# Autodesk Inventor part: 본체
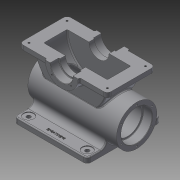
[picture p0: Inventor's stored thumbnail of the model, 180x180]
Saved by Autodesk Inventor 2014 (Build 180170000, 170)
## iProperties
Created: 2023-06
Part Number: 본체
Material: 알루미늄 6061
Document SubType Name: Modeling
Designer: mdu-01
Mass: 5644.39 g
Surface Area: 2847.06 cm^2
Volume: 2082.8 cm^3
Density: 2.71 g/cm^3
Appearance: 알루미늄 - 평지
Author: mdu-01
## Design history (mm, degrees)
sketch "스케치1"
  geometry: L1 (0, 70)-(0, -70); L2 (0, 0)-(-100, 0); L3 (0, 70)-(-45, 70); L4 (-45, 70)-(-45, 45); L5 (-45, 45)-(-100, 45); L6 (0, -70)-(-45, -70); L7 (-45, -70)-(-45, -45); L8 (-45, -45)-(-100, -45); L9 (-100, 45)-(-100, -45); 1 further point
  constraints: 18 end point, 3 perpendicular, 3 symmetric about line, 2 midpoint, 2 parallel, 1 coincident, 1 vertical
  dimensions: "d0" = 140 distance of L1.start L1.end; "d1" = 100 distance of L2.start L2.end; "d3" = 90 diameter of L4 L1; "d4" = 90 distance between parallel lines of L8 L5
revolve "회전1" sketch "스케치1" stored, may be unused: angle "d5" = 180 deg
sketch "스케치2"
  geometry: L1 (-155, -20)-(65, -20); L2 (75, -10)-(75, 100); L3 (65, 110)-(-155, 110); L4 (-165, 100)-(-165, -10); L5 (-165, -20)-(75, 110); L6 (75, -20)-(-165, 110); A1 r 10 centre (-155, 100) between (-155, 110) and (-165, 100); A2 r 10 centre (65, 100) between (75, 100) and (65, 110); A3 r 10 centre (65, -10) between (65, -20) and (75, -10); A4 r 10 centre (-155, -10) between (-165, -10) and (-155, -20); 1 further point
  constraints: 12 end point, 8 point on circle, 8 point on line, 8 tangent, 4 centre point, 3 equal radius, 2 midpoint, 2 parallel, 1 horizontal, 1 perpendicular
  dimensions: "d6" = 240 distance of L6.end L5.end; "d7" = 130 distance of L5.end L6.start; "d8" = 10 radius of A1
extrude "돌출1" join sketch "스케치2" distance "d9" = 15; taper "d10" = 0 deg
sketch "스케치3"
  geometry: C1 r 55 at (-100, 0); 1 further point
  constraints: 1 centre point
  dimensions: "d11" = 110 diameter of C1; "d12" = 100 distance of C1.centre point (0, 0)
extrude "돌출2" join sketch "스케치3" distance "d13" = 135; taper "d15" = 0 deg; dims "d14" = 107, "d16" = 0
sketch "스케치4"
  geometry: L1 (-100, -160)-(100, -160); L2 (100, -160)-(100, -145); L3 (100, -145)-(-100, -145); L4 (-100, -145)-(-100, -160); 1 further point
  constraints: 8 end point, 2 parallel, 1 horizontal, 1 perpendicular
  dimensions: "d17" = 200 distance of L3.end L2.end; "d18" = 15 distance of L2.end L1.end; "d19" = 100 distance from line of L4 point (0, 0); "d20" = 160 distance from line of L1 point (0, 0)
extrude "돌출3" join sketch "스케치4" stored distance "d21" = 200; taper "d22" = 0 deg
fillet "모깎기1" dims "d23" = 15
fillet "모깎기2" dims "d24" = 10
sketch "스케치5"
  geometry: L1 (0, 70)-(0, -70); L2 (-45, 70)-(0, 70) reference; L3 (-45, -70)-(0, -70) reference; L4 (-31, 70)-(-31, 48); L5 (-30, 47)-(-27.5, 47); L6 (-27.5, 47)-(-27.5, 32); L7 (-27.5, 32)-(-87, 32); L8 (0, 0)-(-91.923, 0); L9 (-31, -70)-(-31, -48); L10 (-30, -47)-(-27.5, -47); L11 (-27.5, -47)-(-27.5, -32); L12 (-27.5, -32)-(-87, -32); L13 (-87, 32)-(-87, -32); L14 (-31, 70)-(0, 70); L15 (-31, -70)-(0, -70); A1 r 1 centre (-30, 48) between (-31, 48) and (-30, 47); A2 r 1 centre (-30, -48) between (-30, -47) and (-31, -48)
  constraints: 26 end point, 7 symmetric about line, 4 parallel, 4 point on circle, 3 perpendicular, 2 centre point, 2 tangent, 1 collinear, 1 point on line, 1 vertical, 1 other
  dimensions: "d25" = 1 radius of A1; "d26" = 62 diameter of L4 L1; "d27" = 23 distance between parallel lines of L2 L5; "d28" = 64 distance between parallel lines of L12 L7; "d29" = 55 diameter of L6 L1; "d30" = 87 distance between parallel lines of L13 L1
revolve "회전2" sketch "스케치5" stored, may be unused: angle "d31" = 180 deg
sketch "스케치6"
  geometry: L1 (-107, -45)-(-107, -155) reference; L2 (135, -155)-(135, -45) reference; L3 (-107, -100)-(135, -100); L4 (-107, -142.5)-(-83.1, -142.5); L5 (-82, -141.4)-(-82, -138.5); L6 (-82, -138.5)-(110, -138.5); L7 (110, -138.5)-(110, -141.4); L8 (111.1, -142.5)-(135, -142.5); A1 r 1.1 centre (-83.1, -141.4) between (-83.1, -142.5) and (-82, -141.4); A2 r 1.1 centre (111.1, -141.4) between (110, -141.4) and (111.1, -142.5); 1 further point
  constraints: 12 end point, 4 point on circle, 4 tangent, 3 parallel, 2 centre point, 2 collinear, 2 midpoint, 2 perpendicular, 2 point on line, 1 equal radius
  dimensions: "d32" = 1.1 radius of A1; "d33" = 25 distance between parallel lines of L5 L1; "d34" = 77 diameter of L6 L3; "d35" = 85 diameter of L4 L3
revolve "회전3" sketch "스케치6" stored, may be unused: angle "d36" = 180 deg
fillet "모깎기3" dims "d37" = 3
fillet "모깎기4" dims "d38" = 3
sketch "스케치7"
  geometry: L1 (17, -16.754)-(177, -16.754); L2 (177, -16.754)-(177, 143.246); L3 (177, 143.246)-(17, 143.246); L4 (17, 143.246)-(17, -16.754); L5 (17, -16.754)-(177, 143.246); L6 (177, -16.754)-(17, 143.246); 1 further point
  constraints: 12 end point, 2 midpoint, 2 parallel, 1 horizontal, 1 perpendicular
  dimensions: "d39" = 160 distance of L3.end L2.end; "d40" = 160 distance of L2.end L1.end
hole "구멍1" sketch "스케치7" at (17, -16.754), (177, -16.754), (177, 143.246), (17, 143.246) diameter "d41" = 11; stored, may be unused: countersink angle "d45" = 90 deg, drill point angle "d47" = 118 deg; dims "d42" = 6, "d43" = 28, "d44" = 2, "d46" = 8
sketch "스케치8"
  geometry: L1 (-227, 3)-(-13, 3); L2 (-13, 3)-(-13, 107); L3 (-13, 107)-(-227, 107); L4 (-227, 107)-(-227, 3); L5 (-227, 3)-(-13, 107); L6 (-13, 3)-(-227, 107); 1 further point
  constraints: 12 end point, 2 midpoint, 2 parallel, 1 horizontal, 1 perpendicular
  dimensions: "d48" = 214 distance of L3.end L2.end; "d49" = 104 distance of L2.end L1.end
hole "구멍2" sketch "스케치8" at (-227, 3), (-13, 3), (-13, 107), (-227, 107) diameter "d50" = 4.917; stored, may be unused: countersink angle "d54" = 90 deg, drill point angle "d56" = 118 deg; dims "d51" = 15, "d52" = 4, "d53" = 7.5, "d55" = 15
sketch "스케치9"
  geometry: A1 r 37 centre (0, 0) between (-26.163, -26.163) and (26.163, -26.163); 1 further point
  constraints: 2 point on circle, 1 centre point, 1 coincident, 1 horizontal alignment
  dimensions: "d57" = 37 radius of A1; "d58" = 90 deg dimension on A1.centre A1.end A1.start
hole "구멍3" sketch "스케치9" at (-26.163, -26.163), (26.163, -26.163) diameter "d60" = 4.134; stored, may be unused: countersink angle "d64" = 90 deg, drill point angle "d66" = 118 deg; dims "d61" = 10, "d62" = 4, "d63" = 7.5, "d65" = 12
sketch "스케치10" dims "d68" = 97
  geometry: C1 r 38.5 at (0, 0) reference; 3 further points
  constraints: 2 vertical alignment, 1 coincident, 2 other
hole "구멍4" sketch "스케치10" at (0, 48.5) diameter "d70" = 4.134; stored, may be unused: countersink angle "d74" = 90 deg, drill point angle "d76" = 118 deg; dims "d71" = 10, "d72" = 4, "d73" = 7.5, "d75" = 12
node "작업 평면1"
sketch "스케치11"
  geometry: L1 (7, -36.754)-(187, -36.754) reference; 2 further points
  constraints: 1 vertical alignment, 1 other
  dimensions: "d80" = 15 distance from line of point (97, -21.754) L1
feature "엠보싱1" sketch "스케치11" dims "d0" = 140, "d1" = 100, "d3" = 90, "d4" = 90, "d6" = 240, "d7" = 130, "d8" = 10, "d81" = 0.5, "d82" = 0
chamfer "모따기1" distance "d83" = 1; stored, may be unused: second distance "d84" = 2, angle "d85" = 45 deg
node "솔리드1"
mirror "대칭1"
pattern_circular "원형 패턴1" dims angle "d78" = 360 deg
mirror "대칭2"
